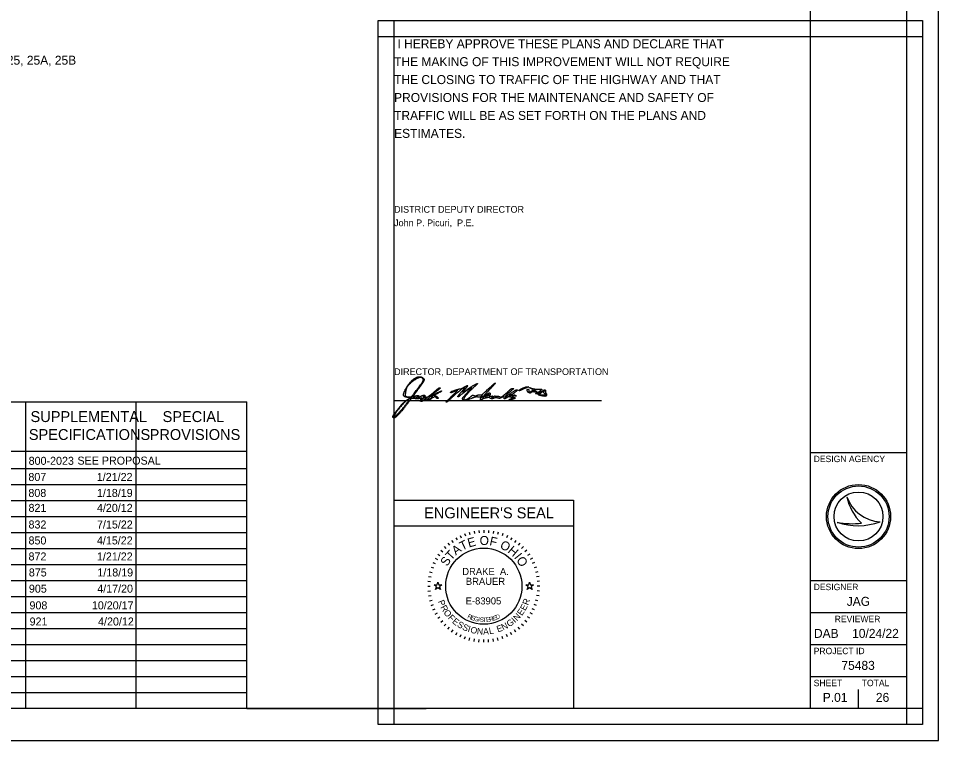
# Model space of a CAD drawing. Extents: x -17.5 to 72.9, y -57.8 to 32.3.
# Drawn here: x 19.64 to 34, y 0 to 11.28 of the extents above; entities that cross this region are included whole.
import ezdxf

# ---------------------------------------------------------------- set-up
doc = ezdxf.new("R2010")
doc.units = 0
for name, color, linetype in [('Default', 7, 'Continuous'), ('SC_Scratch2', 7, 'Continuous'), ('SH_Border', 7, 'Continuous'), ('SH_Cut_Line', 7, 'Continuous'), ('SH_Data', 7, 'Continuous'), ('SH_Text', 7, 'Continuous')]:
    doc.layers.add(name, color=color, linetype=linetype)

msp = doc.modelspace()

# ---------------------------------------------------------------- linework, layer by layer
at = {"layer": 'Default'}
for points in [[(26.124, 2.432), (26.171, 2.432), (26.185, 2.476), (26.199, 2.432), (26.246, 2.432), (26.208, 2.404), (26.223, 2.359), (26.185, 2.387), (26.147, 2.359), (26.162, 2.404)], [(27.554, 2.432), (27.601, 2.432), (27.615, 2.476), (27.629, 2.432), (27.676, 2.432), (27.638, 2.404), (27.653, 2.359), (27.615, 2.387), (27.577, 2.359), (27.592, 2.404)]]:
    msp.add_lwpolyline(points, close=True, dxfattribs=at)
at = {"layer": 'SC_Scratch2'}
for p, q in [((25.25, 0.25), (25.25, 11.25)), ((25.25, 11.25), (33.75, 11.25)), ((25.5, 0.25), (25.5, 11.25)), ((33.5, 11.25), (33.5, 0.25)), ((33.75, 11.25), (33.75, 0.25)), ((25.25, 11), (33.75, 11)), ((33.75, 0.5), (25.25, 0.5)), ((33.75, 0.25), (25.25, 0.25))]:
    msp.add_line(p, q, dxfattribs=at)
at = {"layer": 'SH_Border'}
for p, q in [((32, 0.5), (32, 21.5)), ((32, 4.5), (33.5, 4.5)), ((32, 2.5), (33.5, 2.5)), ((32, 2), (33.5, 2)), ((32, 1.5), (33.5, 1.5)), ((32, 1), (33.5, 1))]:
    msp.add_line(p, q, dxfattribs=at)
msp.add_lwpolyline([(1.5, 21.5), (33.5, 21.5), (33.5, 0.5), (1.5, 0.5)], close=True, dxfattribs=at)
at = {"layer": 'SH_Cut_Line'}
msp.add_lwpolyline([(0, 0), (34, 0), (34, 22), (0, 22)], close=True, dxfattribs=at)
at = {"layer": 'SH_Data'}
for p, q in [((25.5, 5.315), (28.736, 5.315)), ((9.75, 5.292), (23.2, 5.292)), ((19.75, 0.5), (19.75, 5.292)), ((21.475, 0.5), (21.475, 5.292)), ((23.2, 0.5), (23.2, 5.292)), ((23.2, 0.5), (23.2, 5.292)), ((9.75, 4.521), (23.2, 4.521)), ((9.75, 4.25), (23.2, 4.25)), ((9.75, 4), (23.2, 4)), ((9.75, 3.75), (23.2, 3.75)), ((25.5, 0.507), (25.5, 3.757)), ((25.5, 0.507), (25.5, 3.757)), ((25.5, 3.757), (28.3, 3.757)), ((28.3, 3.757), (28.3, 0.507)), ((32.567, 3.81), (32.567, 3.81)), ((9.75, 3.5), (23.2, 3.5)), ((32.75, 3.5), (32.75, 3.5)), ((25.5, 3.357), (28.3, 3.357)), ((32.417, 3.41), (32.417, 3.41)), ((33.087, 3.419), (33.087, 3.419)), ((9.75, 3.25), (23.2, 3.25)), ((26.463, 3.169), (26.482, 3.135)), ((26.53, 3.205), (26.547, 3.168)), ((26.601, 3.234), (26.614, 3.196)), ((26.674, 3.257), (26.684, 3.218)), ((26.748, 3.273), (26.755, 3.234)), ((26.824, 3.283), (26.827, 3.243)), ((26.9, 3.287), (26.9, 3.247)), ((26.976, 3.283), (26.973, 3.243)), ((27.052, 3.273), (27.045, 3.234)), ((27.126, 3.257), (27.116, 3.218)), ((27.199, 3.234), (27.186, 3.196)), ((27.27, 3.205), (27.253, 3.168)), ((27.337, 3.169), (27.317, 3.135)), ((26.281, 3.03), (26.31, 3.002)), ((26.338, 3.082), (26.363, 3.051)), ((26.398, 3.128), (26.421, 3.096)), ((27.402, 3.128), (27.379, 3.096)), ((27.462, 3.082), (27.437, 3.051)), ((27.519, 3.03), (27.49, 3.002)), ((9.75, 3), (23.2, 3)), ((26.183, 2.914), (26.216, 2.891)), ((26.23, 2.974), (26.26, 2.948)), ((27.57, 2.974), (27.54, 2.948)), ((27.617, 2.914), (27.584, 2.891)), ((9.75, 2.75), (23.2, 2.75)), ((26.107, 2.781), (26.143, 2.765)), ((26.142, 2.849), (26.177, 2.829)), ((27.658, 2.849), (27.623, 2.829)), ((27.693, 2.781), (27.657, 2.765)), ((26.055, 2.638), (26.093, 2.628)), ((26.078, 2.711), (26.115, 2.697)), ((27.722, 2.711), (27.685, 2.697)), ((27.745, 2.638), (27.707, 2.628)), ((9.75, 2.5), (23.2, 2.5)), ((26.028, 2.488), (26.068, 2.484)), ((26.038, 2.564), (26.078, 2.557)), ((27.762, 2.564), (27.722, 2.557)), ((27.772, 2.488), (27.732, 2.484)), ((26.025, 2.412), (26.065, 2.412)), ((26.028, 2.335), (26.068, 2.339)), ((27.772, 2.335), (27.732, 2.339)), ((27.775, 2.412), (27.735, 2.412)), ((9.75, 2.25), (23.2, 2.25)), ((26.038, 2.26), (26.078, 2.267)), ((26.055, 2.185), (26.093, 2.196)), ((27.745, 2.185), (27.707, 2.196)), ((27.762, 2.26), (27.722, 2.267)), ((26.078, 2.112), (26.115, 2.126)), ((26.107, 2.042), (26.143, 2.059)), ((27.693, 2.042), (27.657, 2.059)), ((27.722, 2.112), (27.685, 2.126)), ((9.75, 2), (23.2, 2)), ((26.142, 1.974), (26.177, 1.994)), ((26.183, 1.91), (26.216, 1.933)), ((26.23, 1.849), (26.26, 1.875)), ((27.57, 1.849), (27.54, 1.875)), ((27.617, 1.91), (27.584, 1.933)), ((27.658, 1.974), (27.623, 1.994)), ((9.75, 1.75), (23.2, 1.75)), ((26.281, 1.793), (26.31, 1.821)), ((26.338, 1.741), (26.363, 1.772)), ((26.398, 1.695), (26.421, 1.728)), ((27.402, 1.695), (27.379, 1.728)), ((27.462, 1.741), (27.437, 1.772)), ((27.519, 1.793), (27.49, 1.821)), ((26.463, 1.654), (26.482, 1.688)), ((26.53, 1.619), (26.547, 1.655)), ((26.601, 1.589), (26.614, 1.627)), ((26.674, 1.566), (26.684, 1.605)), ((26.748, 1.55), (26.755, 1.589)), ((27.052, 1.55), (27.045, 1.589)), ((27.126, 1.566), (27.116, 1.605)), ((27.199, 1.589), (27.186, 1.627)), ((27.27, 1.619), (27.253, 1.655)), ((27.337, 1.654), (27.317, 1.688)), ((9.75, 1.5), (23.2, 1.5)), ((26.824, 1.54), (26.827, 1.58)), ((26.9, 1.537), (26.9, 1.577)), ((26.976, 1.54), (26.973, 1.58)), ((9.75, 1.25), (23.2, 1.25)), ((9.75, 1), (23.2, 1)), ((9.75, 0.75), (23.2, 0.75)), ((32.75, 0.5), (32.75, 0.8)), ((32.375, 0.675), (32.375, 0.675)), ((23.2, 0.5), (26, 0.5)), ((23.2, 0.5), (26, 0.5)), ((25.5, 0.507), (28.3, 0.507)), ((25.5, 0.507), (28.3, 0.507))]:
    msp.add_line(p, q, dxfattribs=at)
for centre, radius in [((32.75, 3.5), 0.5), ((32.75, 3.5), 0.477), ((32.75, 3.5), 0.477), ((32.75, 3.5), 0.382), ((26.9, 2.412), 0.595)]:
    msp.add_circle(centre, radius, dxfattribs=at)
for centre, radius, start, end in [((33.116, 3.998), 0.58, 198.9257, 198.9319), ((33.347, 3.97), 0.796, 191.6379, 191.6421), ((33.116, 3.998), 0.58, 198.9319, 267.1657), ((33.347, 3.97), 0.796, 191.6421, 226.0947), ((32.739, 4.37), 1.013, 251.4576, 290.0832), ((32.648, 4.654), 1.266, 259.4964, 259.4995), ((32.739, 4.37), 1.013, 251.4527, 251.4576), ((32.648, 4.654), 1.266, 259.4995, 276.6672)]:
    msp.add_arc(centre, radius, start, end, dxfattribs=at)
at = {"layer": 'SH_Text'}
for p, q in [((25.847, 5.469), (25.847, 5.469)), ((27.451, 5.468), (27.451, 5.468)), ((26.087, 5.37), (26.087, 5.37)), ((26.121, 5.402), (26.121, 5.402)), ((26.4, 5.38), (26.4, 5.38)), ((26.982, 5.403), (26.982, 5.403)), ((27.791, 5.389), (27.791, 5.389)), ((25.482, 5.065), (25.482, 5.065)), ((25.569, 5.115), (25.569, 5.115))]:
    msp.add_line(p, q, dxfattribs=at)
for points in [[(27.649, 5.461), (27.676, 5.477), (27.646, 5.495)], [(25.736, 5.344), (25.759, 5.36), (25.731, 5.36)], [(25.918, 5.329), (25.934, 5.353), (25.903, 5.346)], [(26.944, 5.388), (26.922, 5.369), (26.952, 5.384)], [(27.836, 5.399), (27.878, 5.399), (27.856, 5.415)]]:
    msp.add_lwpolyline(points, dxfattribs=at)
for points in [[(25.688, 5.507), (25.753, 5.62), (25.909, 5.707), (25.958, 5.658)], [(25.952, 5.651), (25.932, 5.682), (25.838, 5.652), (25.766, 5.59)], [(25.847, 5.469), (25.938, 5.592), (25.962, 5.634), (25.952, 5.651)], [(25.959, 5.611), (25.95, 5.594), (25.912, 5.537), (25.872, 5.485)], [(25.958, 5.658), (25.972, 5.644), (25.972, 5.64), (25.959, 5.611)], [(25.731, 5.36), (25.657, 5.362), (25.64, 5.422), (25.688, 5.507)], [(25.766, 5.59), (25.716, 5.548), (25.687, 5.499), (25.679, 5.446)], [(25.737, 5.37), (25.772, 5.37), (25.776, 5.373), (25.847, 5.469)], [(25.872, 5.485), (25.833, 5.433), (25.801, 5.388), (25.801, 5.384)], [(26.121, 5.402), (26.136, 5.415), (26.235, 5.464), (26.239, 5.461)], [(26.239, 5.461), (26.244, 5.456), (26.137, 5.398), (26.123, 5.398)], [(26.131, 5.452), (26.169, 5.484), (26.203, 5.511), (26.207, 5.511)], [(26.207, 5.511), (26.225, 5.511), (26.208, 5.492), (26.143, 5.441)], [(26.605, 5.516), (26.598, 5.523), (26.441, 5.398), (26.382, 5.339)], [(26.383, 5.443), (26.383, 5.451), (26.523, 5.498), (26.535, 5.494)], [(26.4, 5.38), (26.453, 5.431), (26.494, 5.473), (26.492, 5.473)], [(26.492, 5.473), (26.489, 5.473), (26.467, 5.465), (26.443, 5.455)], [(26.711, 5.516), (26.674, 5.495), (26.533, 5.396), (26.523, 5.384)], [(26.535, 5.494), (26.539, 5.493), (26.561, 5.503), (26.584, 5.516)], [(26.547, 5.441), (26.582, 5.48), (26.608, 5.513), (26.605, 5.516)], [(26.608, 5.49), (26.587, 5.467), (26.57, 5.444), (26.57, 5.441)], [(26.57, 5.441), (26.57, 5.438), (26.596, 5.453), (26.629, 5.476)], [(26.584, 5.516), (26.643, 5.551), (26.653, 5.541), (26.608, 5.49)], [(26.73, 5.505), (26.656, 5.435), (26.589, 5.354), (26.589, 5.334)], [(26.629, 5.476), (26.689, 5.519), (26.787, 5.576), (26.799, 5.576)], [(26.662, 5.456), (26.696, 5.493), (26.718, 5.52), (26.711, 5.516)], [(26.799, 5.576), (26.803, 5.576), (26.772, 5.544), (26.73, 5.505)], [(26.838, 5.4), (26.863, 5.397), (26.881, 5.41), (26.969, 5.491)], [(26.993, 5.485), (26.895, 5.382), (26.871, 5.347), (26.933, 5.398)], [(26.969, 5.491), (27.025, 5.543), (27.075, 5.586), (27.079, 5.586)], [(27.079, 5.586), (27.084, 5.586), (27.045, 5.541), (26.993, 5.485)], [(27.329, 5.466), (27.274, 5.42), (27.236, 5.38), (27.236, 5.367)], [(27.261, 5.381), (27.302, 5.417), (27.412, 5.485), (27.424, 5.481)], [(27.275, 5.449), (27.309, 5.482), (27.337, 5.501), (27.35, 5.501)], [(27.35, 5.501), (27.369, 5.501), (27.366, 5.496), (27.329, 5.466)], [(27.424, 5.481), (27.431, 5.479), (27.419, 5.465), (27.399, 5.449)], [(27.451, 5.468), (27.451, 5.478), (27.566, 5.531), (27.58, 5.528)], [(27.505, 5.484), (27.458, 5.463), (27.451, 5.461), (27.451, 5.468)], [(27.58, 5.528), (27.596, 5.525), (27.596, 5.525), (27.505, 5.484)], [(27.602, 5.435), (27.582, 5.446), (27.574, 5.492), (27.592, 5.492)], [(27.592, 5.492), (27.597, 5.492), (27.601, 5.482), (27.601, 5.469)], [(27.601, 5.469), (27.601, 5.441), (27.612, 5.439), (27.649, 5.461)], [(27.646, 5.495), (27.614, 5.513), (27.613, 5.513), (27.69, 5.493)], [(27.694, 5.458), (27.712, 5.48), (27.7, 5.477), (27.658, 5.449)], [(27.69, 5.493), (27.706, 5.489), (27.739, 5.487), (27.765, 5.488)], [(27.765, 5.488), (27.806, 5.491), (27.81, 5.489), (27.795, 5.478)], [(27.795, 5.478), (27.774, 5.462), (27.791, 5.45), (27.816, 5.464)], [(27.841, 5.449), (27.849, 5.469), (27.843, 5.466), (27.796, 5.432)], [(27.816, 5.464), (27.846, 5.48), (27.864, 5.475), (27.864, 5.452)], [(25.731, 5.322), (25.715, 5.338), (25.551, 5.168), (25.516, 5.101)], [(25.548, 5.162), (25.606, 5.238), (25.666, 5.296), (25.736, 5.344)], [(25.569, 5.115), (25.62, 5.167), (25.736, 5.316), (25.731, 5.322)], [(25.679, 5.446), (25.67, 5.391), (25.686, 5.37), (25.737, 5.37)], [(25.797, 5.344), (25.772, 5.346), (25.763, 5.339), (25.706, 5.262)], [(25.806, 5.37), (25.789, 5.369), (25.789, 5.368), (25.809, 5.36)], [(25.903, 5.346), (25.873, 5.338), (25.856, 5.338), (25.797, 5.344)], [(25.801, 5.384), (25.801, 5.38), (25.813, 5.38), (25.827, 5.384)], [(25.839, 5.38), (25.831, 5.375), (25.816, 5.37), (25.806, 5.37)], [(25.809, 5.36), (25.831, 5.351), (25.874, 5.37), (25.861, 5.383)], [(25.827, 5.384), (25.846, 5.388), (25.849, 5.387), (25.839, 5.38)], [(25.861, 5.383), (25.857, 5.386), (25.862, 5.389), (25.871, 5.389)], [(25.871, 5.389), (25.882, 5.389), (25.886, 5.384), (25.882, 5.375)], [(25.882, 5.375), (25.875, 5.357), (25.885, 5.357), (25.909, 5.373)], [(25.917, 5.299), (25.904, 5.304), (25.904, 5.307), (25.918, 5.329)], [(25.909, 5.373), (25.931, 5.388), (25.979, 5.401), (25.979, 5.393)], [(25.968, 5.352), (25.93, 5.331), (25.915, 5.314), (25.935, 5.314)], [(25.935, 5.314), (25.952, 5.314), (26.047, 5.381), (26.131, 5.452)], [(25.963, 5.374), (25.949, 5.364), (25.95, 5.363), (25.975, 5.367)], [(25.979, 5.393), (25.979, 5.389), (25.972, 5.381), (25.963, 5.374)], [(26.006, 5.324), (26.003, 5.331), (25.989, 5.327), (25.967, 5.314)], [(25.975, 5.367), (26.002, 5.371), (26.002, 5.371), (25.968, 5.352)], [(26.091, 5.347), (26.04, 5.313), (26.012, 5.306), (26.006, 5.324)], [(26.047, 5.358), (26.014, 5.328), (26.023, 5.321), (26.066, 5.343)], [(26.087, 5.37), (26.074, 5.375), (26.062, 5.371), (26.047, 5.358)], [(26.143, 5.441), (26.073, 5.387), (26.057, 5.371), (26.09, 5.388)], [(26.066, 5.343), (26.101, 5.361), (26.103, 5.364), (26.087, 5.37)], [(26.09, 5.388), (26.1, 5.393), (26.118, 5.395), (26.13, 5.392)], [(26.155, 5.361), (26.142, 5.379), (26.141, 5.378), (26.091, 5.347)], [(26.123, 5.398), (26.12, 5.398), (26.119, 5.4), (26.121, 5.402)], [(26.13, 5.392), (26.157, 5.385), (26.201, 5.342), (26.181, 5.342)], [(26.181, 5.342), (26.174, 5.342), (26.162, 5.35), (26.155, 5.361)], [(26.317, 5.286), (26.309, 5.286), (26.346, 5.329), (26.4, 5.38)], [(26.382, 5.339), (26.354, 5.31), (26.325, 5.286), (26.317, 5.286)], [(26.443, 5.455), (26.396, 5.434), (26.382, 5.432), (26.383, 5.443)], [(26.498, 5.37), (26.49, 5.37), (26.512, 5.401), (26.547, 5.441)], [(26.523, 5.384), (26.516, 5.376), (26.505, 5.37), (26.498, 5.37)], [(26.581, 5.317), (26.562, 5.336), (26.584, 5.374), (26.662, 5.456)], [(26.731, 5.353), (26.622, 5.31), (26.595, 5.303), (26.581, 5.317)], [(26.589, 5.334), (26.589, 5.328), (26.595, 5.323), (26.602, 5.323)], [(26.602, 5.323), (26.619, 5.323), (26.68, 5.357), (26.707, 5.381)], [(26.707, 5.381), (26.722, 5.395), (26.732, 5.397), (26.749, 5.39)], [(26.81, 5.366), (26.788, 5.369), (26.758, 5.364), (26.731, 5.353)], [(26.749, 5.39), (26.765, 5.384), (26.779, 5.385), (26.791, 5.392)], [(26.791, 5.392), (26.801, 5.397), (26.822, 5.401), (26.838, 5.4)], [(26.862, 5.377), (26.851, 5.366), (26.835, 5.363), (26.81, 5.366)], [(26.86, 5.323), (26.846, 5.323), (26.85, 5.348), (26.865, 5.361)], [(26.874, 5.331), (26.871, 5.327), (26.865, 5.323), (26.86, 5.323)], [(26.879, 5.382), (26.879, 5.387), (26.872, 5.385), (26.862, 5.377)], [(26.865, 5.361), (26.873, 5.367), (26.879, 5.377), (26.879, 5.382)], [(26.931, 5.351), (26.902, 5.345), (26.876, 5.335), (26.874, 5.331)], [(26.994, 5.353), (26.986, 5.361), (26.971, 5.361), (26.931, 5.351)], [(26.933, 5.398), (26.969, 5.428), (27.001, 5.435), (27.001, 5.414)], [(26.982, 5.403), (26.982, 5.413), (26.964, 5.406), (26.944, 5.388)], [(26.952, 5.384), (26.969, 5.392), (26.982, 5.401), (26.982, 5.403)], [(26.99, 5.391), (26.981, 5.382), (26.986, 5.38), (27.01, 5.38)], [(27.001, 5.414), (27.001, 5.408), (26.996, 5.397), (26.99, 5.391)], [(27.066, 5.351), (27.043, 5.339), (27.007, 5.34), (26.994, 5.353)], [(27.01, 5.38), (27.038, 5.38), (27.04, 5.378), (27.028, 5.364)], [(27.028, 5.364), (27.019, 5.352), (27.024, 5.354), (27.044, 5.368)], [(27.044, 5.368), (27.06, 5.379), (27.076, 5.386), (27.079, 5.383)], [(27.115, 5.351), (27.094, 5.357), (27.077, 5.357), (27.066, 5.351)], [(27.079, 5.383), (27.082, 5.38), (27.099, 5.378), (27.118, 5.378)], [(27.181, 5.36), (27.153, 5.346), (27.139, 5.344), (27.115, 5.351)], [(27.118, 5.378), (27.136, 5.378), (27.151, 5.374), (27.151, 5.369)], [(27.151, 5.369), (27.151, 5.352), (27.223, 5.398), (27.275, 5.449)], [(27.217, 5.36), (27.217, 5.377), (27.216, 5.377), (27.181, 5.36)], [(27.263, 5.357), (27.229, 5.337), (27.217, 5.338), (27.217, 5.36)], [(27.236, 5.367), (27.236, 5.362), (27.247, 5.368), (27.261, 5.381)], [(27.326, 5.363), (27.297, 5.371), (27.284, 5.37), (27.263, 5.357)], [(27.353, 5.333), (27.318, 5.321), (27.282, 5.325), (27.315, 5.337)], [(27.332, 5.404), (27.295, 5.392), (27.309, 5.382), (27.348, 5.392)], [(27.315, 5.337), (27.326, 5.341), (27.34, 5.346), (27.348, 5.349)], [(27.348, 5.349), (27.357, 5.352), (27.348, 5.358), (27.326, 5.363)], [(27.357, 5.416), (27.355, 5.413), (27.343, 5.407), (27.332, 5.404)], [(27.348, 5.392), (27.377, 5.4), (27.388, 5.399), (27.397, 5.39)], [(27.383, 5.385), (27.356, 5.391), (27.346, 5.374), (27.372, 5.364)], [(27.372, 5.364), (27.394, 5.355), (27.388, 5.344), (27.353, 5.333)], [(27.399, 5.449), (27.379, 5.434), (27.36, 5.419), (27.357, 5.416)], [(27.397, 5.39), (27.407, 5.381), (27.404, 5.379), (27.383, 5.385)], [(27.658, 5.449), (27.628, 5.429), (27.618, 5.427), (27.602, 5.435)], [(27.708, 5.449), (27.683, 5.443), (27.682, 5.444), (27.694, 5.458)], [(27.723, 5.441), (27.734, 5.454), (27.733, 5.455), (27.708, 5.449)], [(27.745, 5.434), (27.721, 5.412), (27.704, 5.417), (27.723, 5.441)], [(27.764, 5.425), (27.787, 5.45), (27.77, 5.458), (27.745, 5.434)], [(27.791, 5.389), (27.75, 5.399), (27.745, 5.404), (27.764, 5.425)], [(27.796, 5.432), (27.764, 5.409), (27.776, 5.399), (27.836, 5.399)], [(27.879, 5.394), (27.873, 5.378), (27.842, 5.377), (27.791, 5.389)], [(27.856, 5.415), (27.841, 5.427), (27.837, 5.437), (27.841, 5.449)], [(27.864, 5.452), (27.864, 5.44), (27.868, 5.425), (27.874, 5.42)], [(27.874, 5.42), (27.88, 5.414), (27.882, 5.402), (27.879, 5.394)], [(25.706, 5.262), (25.591, 5.111), (25.482, 5.014), (25.482, 5.065)], [(25.967, 5.314), (25.948, 5.303), (25.926, 5.296), (25.917, 5.299)], [(25.482, 5.065), (25.482, 5.072), (25.512, 5.116), (25.548, 5.162)], [(25.516, 5.101), (25.493, 5.055), (25.517, 5.061), (25.569, 5.115)]]:
    msp.add_open_spline(points, degree=2, dxfattribs=at)

# ---------------------------------------------------------------- texts
at = {"layer": 'SH_Data'}
for s, height, p in [(' I HEREBY APPROVE THESE PLANS AND DECLARE THAT', 0.14, (25.5, 10.815)), ('24-25, 25A, 25B', 0.14, (19.184, 10.558)), ('THE MAKING OF THIS IMPROVEMENT WILL NOT REQUIRE', 0.14, (25.5, 10.535)), ('THE CLOSING TO TRAFFIC OF THE HIGHWAY AND THAT', 0.14, (25.5, 10.255)), ('PROVISIONS FOR THE MAINTENANCE AND SAFETY OF', 0.14, (25.5, 9.975)), ('TRAFFIC WILL BE AS SET FORTH ON THE PLANS AND', 0.14, (25.5, 9.695)), ('ESTIMATES.', 0.14, (25.5, 9.415)), ('DESIGN AGENCY', 0.1, (32.05, 4.35)), ("ENGINEER'S SEAL", 0.17, (25.968, 3.472)), ('DRAKE  A.', 0.11, (26.564, 2.587)), ('BRAUER', 0.11, (26.62, 2.433)), ('DESIGNER', 0.1, (32.05, 2.35)), ('E-83905', 0.11, (26.617, 2.127)), ('JAG', 0.14, (32.566, 2.105)), ('REVIEWER', 0.1, (32.378, 1.85)), ('DAB', 0.14, (32.054, 1.605)), ('10/24/22', 0.14, (32.65, 1.605)), ('PROJECT ID', 0.1, (32.05, 1.35)), ('75483', 0.14, (32.483, 1.105)), ('SHEET', 0.1, (32.05, 0.85)), ('TOTAL', 0.1, (32.8, 0.85)), ('P.01', 0.14, (32.192, 0.605)), ('26', 0.14, (33.021, 0.605))]:
    msp.add_text(s, height=height, dxfattribs=at).set_placement(p)
for s, height, rotation, p in [('E', 0.14, 15.7571, (26.668, 3.015)), ('O', 0.14, 359.7812, (26.835, 3.056)), ('F', 0.14, 347.4362, (26.981, 3.053)), ('A', 0.14, 36.4747, (26.463, 2.89)), ('T', 0.14, 25.7167, (26.562, 2.963)), ('O', 0.14, 332.2586, (27.14, 3.013)), ('H', 0.14, 319.9136, (27.263, 2.948)), ('S', 0.14, 57.1924, (26.328, 2.713)), ('T', 0.14, 46.4344, (26.388, 2.808)), ('I', 0.14, 308.367, (27.366, 2.86)), ('O', 0.14, 303.1491, (27.402, 2.82)), ('P', 0.1, 291.494, (26.182, 2.174)), ('R', 0.1, 69.2322, (27.592, 2.107)), ('R', 0.1, 298.7311, (26.219, 2.083)), ('O', 0.1, 306.4666, (26.265, 2)), ('E', 0.1, 54.758, (27.493, 1.943)), ('E', 0.1, 61.9951, (27.548, 2.021)), ('F', 0.1, 314.7068, (26.334, 1.91)), ('E', 0.1, 321.4393, (26.398, 1.846)), ('R', 0.07, 334.487, (26.637, 1.917)), ('E', 0.07, 341.04, (26.691, 1.892)), ('G', 0.07, 347.4752, (26.741, 1.873)), ('I', 0.07, 353.7858, (26.809, 1.858)), ('S', 0.07, 356.8926, (26.836, 1.855)), ('T', 0.07, 3.0061, (26.886, 1.85)), ('E', 0.07, 6.0117, (26.939, 1.853)), ('R', 0.07, 11.9184, (26.992, 1.859)), ('E', 0.07, 17.6836, (27.05, 1.872)), ('D', 0.07, 23.3052, (27.101, 1.889)), ('G', 0.1, 35.0469, (27.298, 1.769)), ('I', 0.1, 43.287, (27.387, 1.833)), ('N', 0.1, 47.0224, (27.42, 1.862)), ('S', 0.1, 328.6764, (26.474, 1.787)), ('S', 0.1, 335.9134, (26.556, 1.738)), ('I', 0.1, 343.1505, (26.641, 1.701)), ('O', 0.1, 346.8859, (26.684, 1.687)), ('N', 0.1, 355.1261, (26.789, 1.663)), ('A', 0.1, 2.8617, (26.892, 1.655)), ('L', 0.1, 10.0987, (26.989, 1.661)), ('E', 0.1, 20.0742, (27.121, 1.689)), ('N', 0.1, 27.3113, (27.204, 1.719))]:
    msp.add_text(s, height=height, rotation=rotation, dxfattribs=at).set_placement(p)
at = {"layer": 'SH_Text'}
for s, height, p in [('DISTRICT DEPUTY DIRECTOR', 0.105, (25.5, 8.245)), ('John P. Picuri,  P.E.', 0.105, (25.5, 8.035)), ('DIRECTOR, DEPARTMENT OF TRANSPORTATION', 0.105, (25.5, 5.71)), ('SUPPLEMENTAL', 0.17, (19.824, 4.976)), ('SPECIAL', 0.17, (21.886, 4.976)), ('SPECIFICATIONS', 0.17, (19.798, 4.696)), ('PROVISIONS', 0.17, (21.684, 4.696)), ('800-2023', 0.125, (19.795, 4.308)), ('SEE PROPOSAL', 0.125, (20.557, 4.311)), ('807', 0.125, (19.791, 4.056)), ('1/21/22', 0.125, (20.859, 4.056)), ('808', 0.125, (19.791, 3.806)), ('1/18/19', 0.125, (20.861, 3.806)), ('821', 0.125, (19.793, 3.573)), ('4/20/12', 0.125, (20.861, 3.573)), ('832', 0.125, (19.793, 3.313)), ('7/15/22', 0.125, (20.862, 3.313)), ('850', 0.125, (19.793, 3.064)), ('4/15/22', 0.125, (20.861, 3.064)), ('872', 0.125, (19.793, 2.814)), ('1/21/22', 0.125, (20.861, 2.814)), ('875', 0.125, (19.798, 2.564)), ('1/18/19', 0.125, (20.868, 2.564)), ('4/17/20', 0.125, (20.866, 2.311)), ('905', 0.125, (19.799, 2.311)), ('908', 0.125, (19.808, 2.05)), ('10/20/17', 0.125, (20.782, 2.05)), ('921', 0.125, (19.81, 1.798)), ('4/20/12', 0.125, (20.879, 1.798))]:
    msp.add_text(s, height=height, dxfattribs=at).set_placement(p)

doc.saveas('drawing.dxf')
